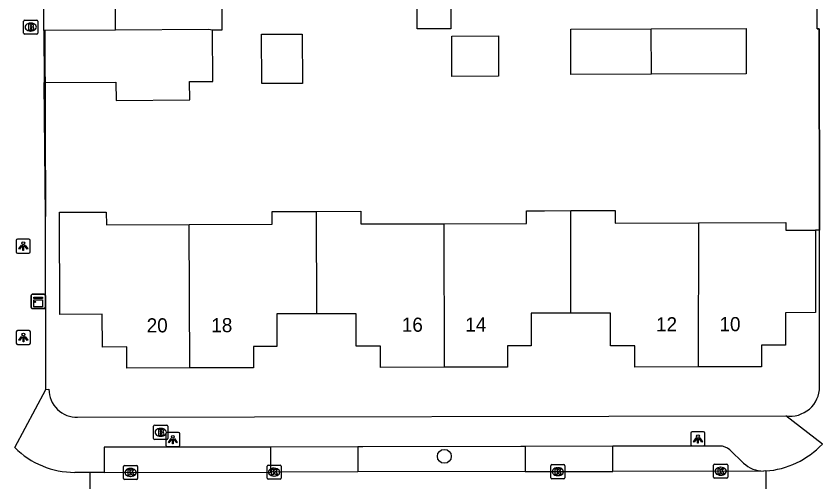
# Model space of a CAD drawing. Extents: x 160457 to 162082, y 388340 to 389736.
# Drawn here: x 160888.4 to 160945.3, y 388459.2 to 388492.2 of the extents above; entities that cross this region are included whole.
import ezdxf

# ---------------------------------------------------------------- set-up
doc = ezdxf.new("R2010")
doc.units = 0
for name, color, linetype in [('IMGEO_Boom', 7, 'Continuous'), ('IMGEO_Brandkraan', 7, 'Continuous'), ('IMGEO_Kast', 7, 'Continuous'), ('IMGEO_Kolk', 7, 'Continuous'), ('IMGEO_Lichtpunt', 7, 'Continuous'), ('IMGEO_Muur', 7, 'Continuous'), ('IMGEO_Pand', 7, 'Continuous'), ('IMGEO_Pand_nummerreeks', 7, 'Continuous'), ('IMGEO_Parkeervlak_open', 7, 'Continuous'), ('IMGEO_Rijbaan_lokaal_open', 7, 'Continuous'), ('IMGEO_Voetpad_open', 7, 'Continuous')]:
    doc.layers.add(name, color=color, linetype=linetype)

msp = doc.modelspace()

# ---------------------------------------------------------------- linework, layer by layer
at = {"layer": 'IMGEO_Boom'}
msp.add_circle((160918.666, 388461.014), 0.489, dxfattribs=at)
at = {"layer": 'IMGEO_Brandkraan'}
for p, q in [((160888.89, 388490.964), (160888.89, 388491.816)), ((160888.965, 388491.89), (160889.817, 388491.89)), ((160889.378, 388491.67), (160889.403, 388491.67)), ((160889.891, 388491.816), (160889.891, 388490.964)), ((160889.401, 388491.11), (160889.376, 388491.11)), ((160889.817, 388490.89), (160888.965, 388490.89)), ((160898.091, 388462.287), (160898.091, 388463.139)), ((160898.166, 388463.213), (160899.018, 388463.213)), ((160899.092, 388463.139), (160899.092, 388462.287)), ((160898.579, 388462.993), (160898.604, 388462.993)), ((160899.018, 388462.213), (160898.166, 388462.213)), ((160898.602, 388462.433), (160898.577, 388462.433))]:
    msp.add_line(p, q, dxfattribs=at)
for points in [[(160888.89, 388490.964), (160888.89, 388491.816)], [(160888.965, 388491.89), (160889.817, 388491.89)], [(160889.238, 388491.59), (160889.238, 388491.19), (160889.451, 388491.19)], [(160889.469, 388491.59), (160889.238, 388491.59)], [(160889.417, 388491.509), (160889.363, 388491.509), (160889.363, 388491.433)], [(160889.891, 388491.816), (160889.891, 388490.964)], [(160889.363, 388491.433), (160889.416, 388491.433)], [(160889.425, 388491.357), (160889.363, 388491.357), (160889.363, 388491.276)], [(160889.363, 388491.276), (160889.425, 388491.276)], [(160889.817, 388490.89), (160888.965, 388490.89)], [(160898.091, 388462.287), (160898.091, 388463.139)], [(160898.166, 388463.213), (160899.018, 388463.213)], [(160899.092, 388463.139), (160899.092, 388462.287)], [(160898.439, 388462.913), (160898.439, 388462.513), (160898.652, 388462.513)], [(160898.67, 388462.913), (160898.439, 388462.913)], [(160898.618, 388462.832), (160898.564, 388462.832), (160898.564, 388462.756)], [(160898.564, 388462.756), (160898.617, 388462.756)], [(160898.626, 388462.68), (160898.564, 388462.68), (160898.564, 388462.599)], [(160898.564, 388462.599), (160898.626, 388462.599)], [(160899.018, 388462.213), (160898.166, 388462.213)]]:
    msp.add_lwpolyline(points, dxfattribs=at)
for centre, radius, start, end in [((160888.967, 388491.814), 0.0765, 91.552, 178.448), ((160888.967, 388491.814), 0.0765, 91.552, 178.448), ((160889.418, 388491.471), 0.0379, 267.8285, 90.9355), ((160889.473, 388491.445), 0.145, 59.4692, 91.5367), ((160889.498, 388491.492), 0.0922, 285.5137, 58.1501), ((160889.815, 388491.814), 0.0765, 1.552, 88.448), ((160889.815, 388491.814), 0.0765, 1.552, 88.448), ((160888.967, 388490.966), 0.0765, 181.552, 268.448), ((160888.967, 388490.966), 0.0765, 181.552, 268.448), ((160889.426, 388491.316), 0.0404, 269.8759, 90.5077), ((160889.457, 388491.441), 0.251, 268.6676, 293.5347), ((160889.503, 388491.3), 0.105, 301.3115, 78.989), ((160889.815, 388490.966), 0.0765, 271.552, 358.448), ((160889.815, 388490.966), 0.0765, 271.552, 358.448), ((160898.168, 388463.137), 0.0765, 91.552, 178.448), ((160898.168, 388463.137), 0.0765, 91.552, 178.448), ((160899.016, 388463.137), 0.0765, 1.552, 88.448), ((160899.016, 388463.137), 0.0765, 1.552, 88.448), ((160898.619, 388462.794), 0.0379, 267.8285, 90.9355), ((160898.627, 388462.639), 0.0404, 269.8759, 90.5077), ((160898.658, 388462.764), 0.251, 268.6676, 293.5347), ((160898.674, 388462.768), 0.145, 59.4692, 91.5367), ((160898.699, 388462.815), 0.0922, 285.5137, 58.1501), ((160898.704, 388462.623), 0.105, 301.3115, 78.989), ((160898.168, 388462.289), 0.0765, 181.552, 268.448), ((160898.168, 388462.289), 0.0765, 181.552, 268.448), ((160899.016, 388462.289), 0.0765, 271.552, 358.448), ((160899.016, 388462.289), 0.0765, 271.552, 358.448)]:
    msp.add_arc(centre, radius, start, end, dxfattribs=at)
for centre, major_axis, ratio, start_param, end_param in [((160889.377, 388491.39), (-0.387, 0.002), 0.722429, 4.712389, 7.853982), ((160889.402, 388491.39), (-0.39, 0.002), 0.717154, 1.570796, 4.712389), ((160898.578, 388462.713), (-0.387, 0.002), 0.722429, 4.712389, 7.853982), ((160898.603, 388462.713), (-0.39, 0.002), 0.717154, 1.570796, 4.712389)]:
    msp.add_ellipse(centre, major_axis=major_axis, ratio=ratio, start_param=start_param, end_param=end_param, dxfattribs=at)
at = {"layer": 'IMGEO_Kast'}
for p, q in [((160889.424, 388471.554), (160889.424, 388472.395)), ((160889.424, 388472.395), (160889.424, 388471.554)), ((160889.499, 388472.479), (160890.34, 388472.479)), ((160890.34, 388472.479), (160889.499, 388472.479)), ((160890.424, 388472.404), (160890.424, 388471.563)), ((160890.424, 388471.563), (160890.424, 388472.404)), ((160890.349, 388471.479), (160889.508, 388471.479)), ((160889.508, 388471.479), (160890.349, 388471.479))]:
    msp.add_line(p, q, dxfattribs=at)
for points in [[(160889.619, 388472.269), (160890.219, 388472.269), (160890.219, 388472.184), (160889.619, 388472.184), (160889.619, 388472.269)], [(160889.619, 388472.094), (160890.219, 388472.094), (160890.219, 388471.605), (160889.619, 388471.605), (160889.619, 388472.094)]]:
    msp.add_lwpolyline(points, dxfattribs=at)
msp.add_circle((160889.703, 388471.943), 0.0377, dxfattribs=at)
for centre, start, end in [((160889.502, 388472.401), 92.4484, 184.2845), ((160889.502, 388472.401), 92.4484, 184.2845), ((160890.346, 388472.401), 2.4484, 94.2845), ((160890.346, 388472.401), 2.4484, 94.2845), ((160889.502, 388471.557), 182.4484, 274.2845), ((160889.502, 388471.557), 182.4484, 274.2845), ((160890.346, 388471.557), 272.4484, 4.2845), ((160890.346, 388471.557), 272.4484, 4.2845)]:
    msp.add_arc(centre, 0.0779, start, end, dxfattribs=at)
at = {"layer": 'IMGEO_Kolk'}
for p, q in [((160895.958, 388459.448), (160895.958, 388460.3)), ((160896.033, 388460.374), (160896.885, 388460.374)), ((160896.959, 388460.3), (160896.959, 388459.448)), ((160906.117, 388459.468), (160906.117, 388460.32)), ((160906.192, 388460.394), (160907.044, 388460.394)), ((160906.605, 388460.174), (160906.63, 388460.174)), ((160907.118, 388460.32), (160907.118, 388459.468)), ((160926.199, 388459.499), (160926.199, 388460.351)), ((160926.274, 388460.425), (160927.126, 388460.425)), ((160926.687, 388460.205), (160926.712, 388460.205)), ((160927.2, 388460.351), (160927.2, 388459.499)), ((160937.726, 388459.533), (160937.726, 388460.385)), ((160937.801, 388460.459), (160938.653, 388460.459)), ((160938.214, 388460.239), (160938.239, 388460.239)), ((160938.727, 388460.385), (160938.727, 388459.533)), ((160896.446, 388460.154), (160896.471, 388460.154)), ((160906.628, 388459.614), (160906.603, 388459.614)), ((160926.71, 388459.645), (160926.685, 388459.645)), ((160938.237, 388459.679), (160938.212, 388459.679)), ((160896.885, 388459.374), (160896.033, 388459.374)), ((160896.469, 388459.594), (160896.444, 388459.594)), ((160907.044, 388459.394), (160906.192, 388459.394)), ((160927.126, 388459.425), (160926.274, 388459.425)), ((160938.653, 388459.459), (160937.801, 388459.459))]:
    msp.add_line(p, q, dxfattribs=at)
for points in [[(160895.958, 388459.448), (160895.958, 388460.3)], [(160896.033, 388460.374), (160896.885, 388460.374)], [(160896.959, 388460.3), (160896.959, 388459.448)], [(160906.117, 388459.468), (160906.117, 388460.32)], [(160906.192, 388460.394), (160907.044, 388460.394)], [(160907.118, 388460.32), (160907.118, 388459.468)], [(160926.199, 388459.499), (160926.199, 388460.351)], [(160926.274, 388460.425), (160927.126, 388460.425)], [(160927.2, 388460.351), (160927.2, 388459.499)], [(160937.726, 388459.533), (160937.726, 388460.385)], [(160937.801, 388460.459), (160938.653, 388460.459)], [(160938.727, 388460.385), (160938.727, 388459.533)], [(160896.279, 388460.074), (160896.402, 388460.074), (160896.402, 388459.923), (160896.532, 388460.074), (160896.696, 388460.074), (160896.55, 388459.923), (160896.703, 388459.674), (160896.551, 388459.674), (160896.466, 388459.838), (160896.402, 388459.771), (160896.402, 388459.674), (160896.279, 388459.674), (160896.279, 388460.074)], [(160906.438, 388460.094), (160906.561, 388460.094), (160906.561, 388459.943), (160906.691, 388460.094), (160906.855, 388460.094), (160906.709, 388459.943), (160906.862, 388459.694), (160906.71, 388459.694), (160906.625, 388459.858), (160906.561, 388459.791), (160906.561, 388459.694), (160906.438, 388459.694), (160906.438, 388460.094)], [(160926.52, 388460.125), (160926.643, 388460.125), (160926.643, 388459.974), (160926.773, 388460.125), (160926.937, 388460.125), (160926.791, 388459.974), (160926.944, 388459.725), (160926.792, 388459.725), (160926.707, 388459.889), (160926.643, 388459.822), (160926.643, 388459.725), (160926.52, 388459.725), (160926.52, 388460.125)], [(160938.047, 388460.159), (160938.17, 388460.159), (160938.17, 388460.008), (160938.3, 388460.159), (160938.464, 388460.159), (160938.318, 388460.008), (160938.471, 388459.759), (160938.319, 388459.759), (160938.234, 388459.923), (160938.17, 388459.856), (160938.17, 388459.759), (160938.047, 388459.759), (160938.047, 388460.159)], [(160896.885, 388459.374), (160896.033, 388459.374)], [(160907.044, 388459.394), (160906.192, 388459.394)], [(160927.126, 388459.425), (160926.274, 388459.425)], [(160938.653, 388459.459), (160937.801, 388459.459)]]:
    msp.add_lwpolyline(points, dxfattribs=at)
for centre, start, end in [((160896.035, 388460.298), 91.552, 178.448), ((160896.035, 388460.298), 91.552, 178.448), ((160896.883, 388460.298), 1.552, 88.448), ((160896.883, 388460.298), 1.552, 88.448), ((160906.194, 388460.318), 91.552, 178.448), ((160906.194, 388460.318), 91.552, 178.448), ((160907.042, 388460.318), 1.552, 88.448), ((160907.042, 388460.318), 1.552, 88.448), ((160926.276, 388460.349), 91.552, 178.448), ((160926.276, 388460.349), 91.552, 178.448), ((160927.124, 388460.349), 1.552, 88.448), ((160927.124, 388460.349), 1.552, 88.448), ((160937.803, 388460.383), 91.552, 178.448), ((160937.803, 388460.383), 91.552, 178.448), ((160938.651, 388460.383), 1.552, 88.448), ((160938.651, 388460.383), 1.552, 88.448), ((160896.035, 388459.45), 181.552, 268.448), ((160896.035, 388459.45), 181.552, 268.448), ((160896.883, 388459.45), 271.552, 358.448), ((160896.883, 388459.45), 271.552, 358.448), ((160906.194, 388459.47), 181.552, 268.448), ((160906.194, 388459.47), 181.552, 268.448), ((160907.042, 388459.47), 271.552, 358.448), ((160907.042, 388459.47), 271.552, 358.448), ((160926.276, 388459.501), 181.552, 268.448), ((160926.276, 388459.501), 181.552, 268.448), ((160927.124, 388459.501), 271.552, 358.448), ((160927.124, 388459.501), 271.552, 358.448), ((160937.803, 388459.535), 181.552, 268.448), ((160937.803, 388459.535), 181.552, 268.448), ((160938.651, 388459.535), 271.552, 358.448), ((160938.651, 388459.535), 271.552, 358.448)]:
    msp.add_arc(centre, 0.0765, start, end, dxfattribs=at)
for centre, major_axis, ratio, start_param, end_param in [((160906.604, 388459.894), (-0.387, 0.002), 0.722429, 4.712389, 7.853982), ((160906.629, 388459.894), (-0.39, 0.002), 0.717154, 1.570796, 4.712389), ((160926.686, 388459.925), (-0.387, 0.002), 0.722429, 4.712389, 7.853982), ((160926.711, 388459.925), (-0.39, 0.002), 0.717154, 1.570796, 4.712389), ((160938.213, 388459.959), (-0.387, 0.002), 0.722429, 4.712389, 7.853982), ((160938.238, 388459.959), (-0.39, 0.002), 0.717154, 1.570796, 4.712389), ((160896.445, 388459.874), (-0.387, 0.002), 0.722429, 4.712389, 7.853982), ((160896.47, 388459.874), (-0.39, 0.002), 0.717154, 1.570796, 4.712389)]:
    msp.add_ellipse(centre, major_axis=major_axis, ratio=ratio, start_param=start_param, end_param=end_param, dxfattribs=at)
at = {"layer": 'IMGEO_Lichtpunt'}
for p, q in [((160888.365, 388476.291), (160888.365, 388475.484)), ((160888.365, 388476.291), (160888.365, 388475.484)), ((160889.267, 388476.386), (160888.459, 388476.386)), ((160889.267, 388476.386), (160888.459, 388476.386)), ((160889.361, 388475.484), (160889.361, 388476.291)), ((160889.361, 388475.484), (160889.361, 388476.291)), ((160888.459, 388475.39), (160889.267, 388475.39)), ((160888.459, 388475.39), (160889.267, 388475.39)), ((160889.271, 388469.924), (160888.463, 388469.924)), ((160889.271, 388469.924), (160888.463, 388469.924)), ((160888.369, 388469.829), (160888.369, 388469.022)), ((160888.369, 388469.829), (160888.369, 388469.022)), ((160889.365, 388469.022), (160889.365, 388469.829)), ((160889.365, 388469.022), (160889.365, 388469.829)), ((160888.463, 388468.928), (160889.271, 388468.928)), ((160888.463, 388468.928), (160889.271, 388468.928)), ((160898.95, 388462.602), (160898.95, 388461.795)), ((160898.95, 388462.602), (160898.95, 388461.795)), ((160899.852, 388462.697), (160899.044, 388462.697)), ((160899.852, 388462.697), (160899.044, 388462.697)), ((160899.946, 388461.795), (160899.946, 388462.602)), ((160899.946, 388461.795), (160899.946, 388462.602)), ((160936.121, 388462.648), (160936.121, 388461.841)), ((160936.121, 388462.648), (160936.121, 388461.841)), ((160937.023, 388462.743), (160936.215, 388462.743)), ((160937.023, 388462.743), (160936.215, 388462.743)), ((160937.117, 388461.841), (160937.117, 388462.648)), ((160937.117, 388461.841), (160937.117, 388462.648)), ((160899.044, 388461.701), (160899.852, 388461.701)), ((160899.044, 388461.701), (160899.852, 388461.701)), ((160936.215, 388461.747), (160937.023, 388461.747)), ((160936.215, 388461.747), (160937.023, 388461.747))]:
    msp.add_line(p, q, dxfattribs=at)
for points in [[(160888.739, 388475.955), (160888.778, 388475.927), (160888.59, 388475.665), (160888.552, 388475.692), (160888.739, 388475.955)], [(160888.841, 388475.907), (160888.888, 388475.907), (160888.888, 388475.585), (160888.841, 388475.585), (160888.841, 388475.907)], [(160888.951, 388475.927), (160888.989, 388475.954), (160889.176, 388475.692), (160889.137, 388475.664), (160888.951, 388475.927)], [(160888.743, 388469.493), (160888.782, 388469.465), (160888.594, 388469.203), (160888.556, 388469.23), (160888.743, 388469.493)], [(160888.845, 388469.445), (160888.892, 388469.445), (160888.892, 388469.123), (160888.845, 388469.123), (160888.845, 388469.445)], [(160888.955, 388469.465), (160888.993, 388469.492), (160889.18, 388469.23), (160889.141, 388469.202), (160888.955, 388469.465)], [(160899.324, 388462.266), (160899.363, 388462.238), (160899.175, 388461.976), (160899.137, 388462.003), (160899.324, 388462.266)], [(160899.426, 388462.218), (160899.473, 388462.218), (160899.473, 388461.896), (160899.426, 388461.896), (160899.426, 388462.218)], [(160899.536, 388462.238), (160899.574, 388462.265), (160899.761, 388462.003), (160899.722, 388461.975), (160899.536, 388462.238)], [(160936.495, 388462.312), (160936.534, 388462.284), (160936.346, 388462.022), (160936.308, 388462.049), (160936.495, 388462.312)], [(160936.597, 388462.264), (160936.644, 388462.264), (160936.644, 388461.942), (160936.597, 388461.942), (160936.597, 388462.264)], [(160936.707, 388462.284), (160936.745, 388462.311), (160936.932, 388462.049), (160936.893, 388462.021), (160936.707, 388462.284)]]:
    msp.add_lwpolyline(points, dxfattribs=at)
for centre in [(160888.864, 388476.089), (160888.868, 388469.627), (160899.449, 388462.4), (160936.62, 388462.446)]:
    msp.add_circle(centre, 0.0994, dxfattribs=at)
for centre, start, end in [((160888.459, 388476.291), 90, 180), ((160888.459, 388476.291), 90, 180), ((160889.267, 388476.291), 0, 90), ((160889.267, 388476.291), 0, 90), ((160888.459, 388475.484), 180, 270), ((160888.459, 388475.484), 180, 270), ((160889.267, 388475.484), 270, 0), ((160889.267, 388475.484), 270, 360), ((160888.463, 388469.829), 90, 180), ((160888.463, 388469.829), 90, 180), ((160889.271, 388469.829), 0, 90), ((160889.271, 388469.829), 0, 90), ((160888.463, 388469.022), 180, 270), ((160888.463, 388469.022), 180, 270), ((160889.271, 388469.022), 270, 0), ((160889.271, 388469.022), 270, 360), ((160899.044, 388462.602), 90, 180), ((160899.044, 388462.602), 90, 180), ((160899.852, 388462.602), 0, 90), ((160899.852, 388462.602), 0, 90), ((160936.215, 388462.648), 90, 180), ((160936.215, 388462.648), 90, 180), ((160937.023, 388462.648), 0, 90), ((160937.023, 388462.648), 0, 90), ((160899.044, 388461.795), 180, 270), ((160899.044, 388461.795), 180, 270), ((160899.852, 388461.795), 270, 0), ((160899.852, 388461.795), 270, 360), ((160936.215, 388461.841), 180, 270), ((160936.215, 388461.841), 180, 270), ((160937.023, 388461.841), 270, 0), ((160937.023, 388461.841), 270, 360)]:
    msp.add_arc(centre, 0.0946, start, end, dxfattribs=at)
at = {"layer": 'IMGEO_Muur'}
for points in [[(160890.388, 388491.17), (160890.424, 388477.994)], [(160945.061, 388491.265), (160945.206, 388491.276), (160945.221, 388477.016)], [(160945.221, 388477.016), (160944.944, 388477.018)]]:
    msp.add_lwpolyline(points, dxfattribs=at)
at = {"layer": 'IMGEO_Pand'}
for points in [[(160895.393, 388491.183), (160895.369, 388494.766), (160894.376, 388494.782), (160894.36, 388500), (160894.357, 388500.962)], [(160906.221, 388501.018), (160906.224, 388500), (160906.225, 388499.671), (160906.24, 388494.792), (160902.911, 388494.782), (160902.923, 388491.183), (160902.264, 388491.182)], [(160919.149, 388498.059), (160919.132, 388491.266), (160916.739, 388491.272), (160916.756, 388498.059)], [(160895.393, 388491.183), (160890.322, 388491.158)], [(160890.322, 388491.158), (160890.337, 388487.467)], [(160890.337, 388487.467), (160895.417, 388487.503), (160895.426, 388486.203), (160900.646, 388486.238), (160900.638, 388487.538), (160902.288, 388487.549), (160902.264, 388491.182)], [(160902.264, 388491.182), (160901.985, 388491.215), (160895.393, 388491.183)], [(160933.326, 388488.058), (160927.625, 388488.039), (160927.615, 388491.249), (160933.315, 388491.268)], [(160933.315, 388491.268), (160940.025, 388491.29), (160940.036, 388488.08), (160933.326, 388488.058)], [(160933.326, 388488.058), (160933.315, 388491.268)], [(160905.739, 388487.391), (160905.716, 388490.883), (160908.602, 388490.902), (160908.625, 388487.41), (160905.739, 388487.391)], [(160919.189, 388490.752), (160922.501, 388490.763), (160922.511, 388487.917), (160919.198, 388487.907), (160919.189, 388490.752)], [(160918.626, 388477.477), (160924.486, 388477.496), (160924.484, 388478.396), (160925.765, 388478.4), (160927.614, 388478.406)], [(160927.614, 388478.406), (160930.764, 388478.417), (160930.767, 388477.518), (160936.657, 388477.538)], [(160927.625, 388471.149), (160927.614, 388478.406)], [(160900.647, 388467.272), (160896.189, 388467.257), (160896.184, 388468.756), (160894.464, 388468.75), (160894.456, 388471.069), (160891.446, 388471.059), (160891.422, 388478.283), (160894.741, 388478.296), (160894.745, 388477.396), (160900.614, 388477.416)], [(160900.614, 388477.416), (160906.475, 388477.435), (160906.473, 388478.335), (160909.603, 388478.345)], [(160909.603, 388478.345), (160912.753, 388478.356), (160912.756, 388477.457), (160918.626, 388477.477)], [(160909.603, 388478.345), (160909.628, 388471.103)], [(160900.647, 388467.272), (160900.614, 388477.416)], [(160918.626, 388477.477), (160918.653, 388467.314)], [(160936.657, 388477.538), (160942.847, 388477.559), (160942.849, 388477.01), (160944.944, 388477.018), (160944.939, 388471.203), (160942.826, 388471.18), (160942.827, 388468.882), (160941.122, 388468.877), (160941.125, 388467.357), (160936.645, 388467.345)], [(160936.657, 388477.538), (160936.645, 388467.345)], [(160909.628, 388471.103), (160906.818, 388471.101), (160906.822, 388468.793), (160905.155, 388468.787), (160905.159, 388467.287), (160900.647, 388467.272)], [(160918.653, 388467.314), (160914.153, 388467.304), (160914.149, 388468.803), (160912.429, 388468.799), (160912.424, 388471.105), (160909.628, 388471.103)], [(160927.625, 388471.149), (160924.815, 388471.141), (160924.82, 388468.828), (160923.13, 388468.824), (160923.133, 388467.324), (160918.653, 388467.314)], [(160936.645, 388467.345), (160932.155, 388467.333), (160932.151, 388468.842), (160930.431, 388468.837), (160930.425, 388471.156), (160927.625, 388471.149)]]:
    msp.add_lwpolyline(points, dxfattribs=at)
at = {"layer": 'IMGEO_Parkeervlak_open'}
for points in [[(160906.389, 388459.894), (160906.385, 388461.672)], [(160912.548, 388461.681), (160912.552, 388459.907)], [(160924.381, 388461.7), (160924.385, 388459.932)], [(160930.598, 388459.945), (160930.594, 388461.723)]]:
    msp.add_lwpolyline(points, dxfattribs=at)
at = {"layer": 'IMGEO_Rijbaan_lokaal_open'}
for points in [[(160893.586, 388459.879), (160892.51, 388459.88)], [(160894.578, 388459.869), (160893.586, 388459.879)], [(160893.596, 388455.335), (160893.586, 388459.879)], [(160894.578, 388459.869), (160906.389, 388459.894)], [(160912.552, 388459.907), (160906.389, 388459.894)], [(160924.385, 388459.932), (160912.552, 388459.907)], [(160924.385, 388459.932), (160930.598, 388459.945)], [(160941.256, 388459.968), (160930.598, 388459.945)], [(160941.412, 388459.977), (160941.256, 388459.968)], [(160941.412, 388459.977), (160941.426, 388455.462)]]:
    msp.add_lwpolyline(points, dxfattribs=at)
for centre, radius, start, end in [((160892.491, 388465.861), 5.982, 225.0259, 270.1853), ((160940.978, 388466.08), 6.118, 274.0691, 316.6502)]:
    msp.add_arc(centre, radius, start, end, dxfattribs=at)
at = {"layer": 'IMGEO_Voetpad_open'}
for points in [[(160890.322, 388491.158), (160890.355, 388500), (160890.185, 388545.572), (160904.728, 388545.555), (160916.616, 388545.542)], [(160945.233, 388465.94), (160945.221, 388477.016), (160945.206, 388491.276), (160945.061, 388491.265), (160944.976, 388537.954)], [(160890.451, 388465.733), (160890.424, 388477.994), (160890.337, 388487.467)], [(160888.263, 388461.63), (160890.451, 388465.733)], [(160890.451, 388465.733), (160890.677, 388465.764)], [(160892.712, 388463.775), (160942.837, 388463.879)], [(160945.427, 388461.88), (160942.837, 388463.879)], [(160906.385, 388461.672), (160905.974, 388461.671), (160894.589, 388461.651), (160894.578, 388459.869)], [(160912.548, 388461.681), (160906.385, 388461.672)], [(160924.381, 388461.7), (160924.085, 388461.699), (160912.904, 388461.682), (160912.548, 388461.681)], [(160930.594, 388461.723), (160924.381, 388461.7)], [(160938.16, 388461.744), (160931.032, 388461.725), (160930.594, 388461.723)], [(160939.851, 388460.531), (160938.868, 388461.462)]]:
    msp.add_lwpolyline(points, dxfattribs=at)
for centre, radius, start, end in [((160943.147, 388465.942), 2.086, 261.4477, 359.9554), ((160892.663, 388465.76), 1.986, 179.8984, 271.4115), ((160938.176, 388460.755), 0.989, 45.6302, 90.9346), ((160941.267, 388462.031), 2.063, 226.6433, 269.6836)]:
    msp.add_arc(centre, radius, start, end, dxfattribs=at)

# ---------------------------------------------------------------- texts
at = {"layer": 'IMGEO_Pand_nummerreeks'}
for s, rotation, p in [('20', 0.1916, (160897.6, 388469.781)), ('18', 0.1916, (160902.176, 388469.797)), ('16', 0.1276, (160915.658, 388469.827)), ('14', 0.1276, (160920.148, 388469.837)), ('12', 0.1533, (160933.653, 388469.857)), ('10', 0.1533, (160938.144, 388469.869))]:
    msp.add_text(s, height=1, rotation=rotation, dxfattribs=at).set_placement(p)

doc.saveas('drawing.dxf')
